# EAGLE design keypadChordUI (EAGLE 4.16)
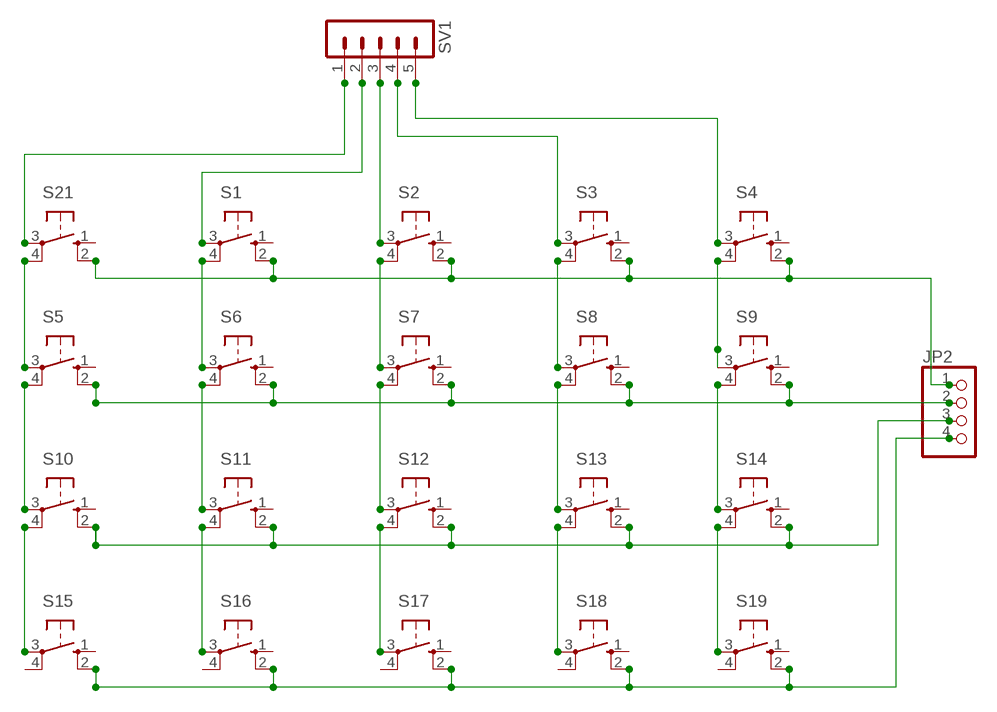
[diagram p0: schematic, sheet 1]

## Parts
JP2  PINHD-1X4  [1X04]
S1  10-XX  [B3F-10XX]
S2  10-XX  [B3F-10XX]
S3  10-XX  [B3F-10XX]
S4  10-XX  [B3F-10XX]
S5  10-XX  [B3F-10XX]
S6  10-XX  [B3F-10XX]
S7  10-XX  [B3F-10XX]
S8  10-XX  [B3F-10XX]
S9  10-XX  [B3F-10XX]
S10  10-XX  [B3F-10XX]
S11  10-XX  [B3F-10XX]
S12  10-XX  [B3F-10XX]
S13  10-XX  [B3F-10XX]
S14  10-XX  [B3F-10XX]
S15  10-XX  [B3F-10XX]
S16  10-XX  [B3F-10XX]
S17  10-XX  [B3F-10XX]
S18  10-XX  [B3F-10XX]
S19  10-XX  [B3F-10XX]
S21  10-XX  [B3F-10XX]
SV1  MA05-1  [MA05-1]

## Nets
N$1: S21.3(P) SV1.1
N$2: S10.4(P1) S15.3(P)
N$3: S4.3(P) SV1.5
N$4: S5.3(P) S21.4(P1)
N$5: S5.4(P1) S10.3(P)
N$7: S1.3(P) SV1.2
N$8: S1.4(P1) S6.3(P)
N$9: S6.4(P1) S11.3(P)
N$10: S2.3(P) SV1.3
N$11: S2.4(P1) S7.3(P)
N$12: S7.4(P1) S12.3(P)
N$13: S3.3(P) SV1.4
N$14: S3.4(P1) S8.3(P)
N$15: S8.4(P1) S13.3(P)
N$16: S14.4(P1) S19.3(P)
N$17: S9.4(P1) S14.3(P)
N$18: S4.4(P1) S9.3(P)
N$19: JP2.4 S15.2(S1) S16.2(S1) S17.2(S1) S18.2(S1) S19.2(S1)
N$21: S11.4(P1) S16.3(P)
N$22: JP2.1 S1.2(S1) S2.2(S1) S3.2(S1) S4.2(S1) S21.2(S1)
N$23: JP2.2 S5.2(S1) S6.2(S1) S7.2(S1) S8.2(S1) S9.2(S1)
N$24: JP2.3 S10.2(S1) S11.2(S1) S12.2(S1) S13.2(S1) S14.2(S1)
N$37: S12.4(P1) S17.3(P)
N$60: S13.4(P1) S18.3(P)
Unconnected: S1.1(S) S2.1(S) S3.1(S) S4.1(S) S5.1(S) S6.1(S) S7.1(S) S8.1(S) S9.1(S) S10.1(S) S11.1(S) S12.1(S) S13.1(S) S14.1(S) S15.1(S) S15.4(P1) S16.1(S) S16.4(P1) S17.1(S) S17.4(P1) S18.1(S) S18.4(P1) S19.1(S) S19.4(P1) S21.1(S)

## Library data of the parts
JP2 = pinhead:PINHD-1X4: PIN HEADER
S1-S19 S21 = switch-omron:10-XX: OMRON SWITCH
SV1 = con-lstb:MA05-1: PIN HEADER

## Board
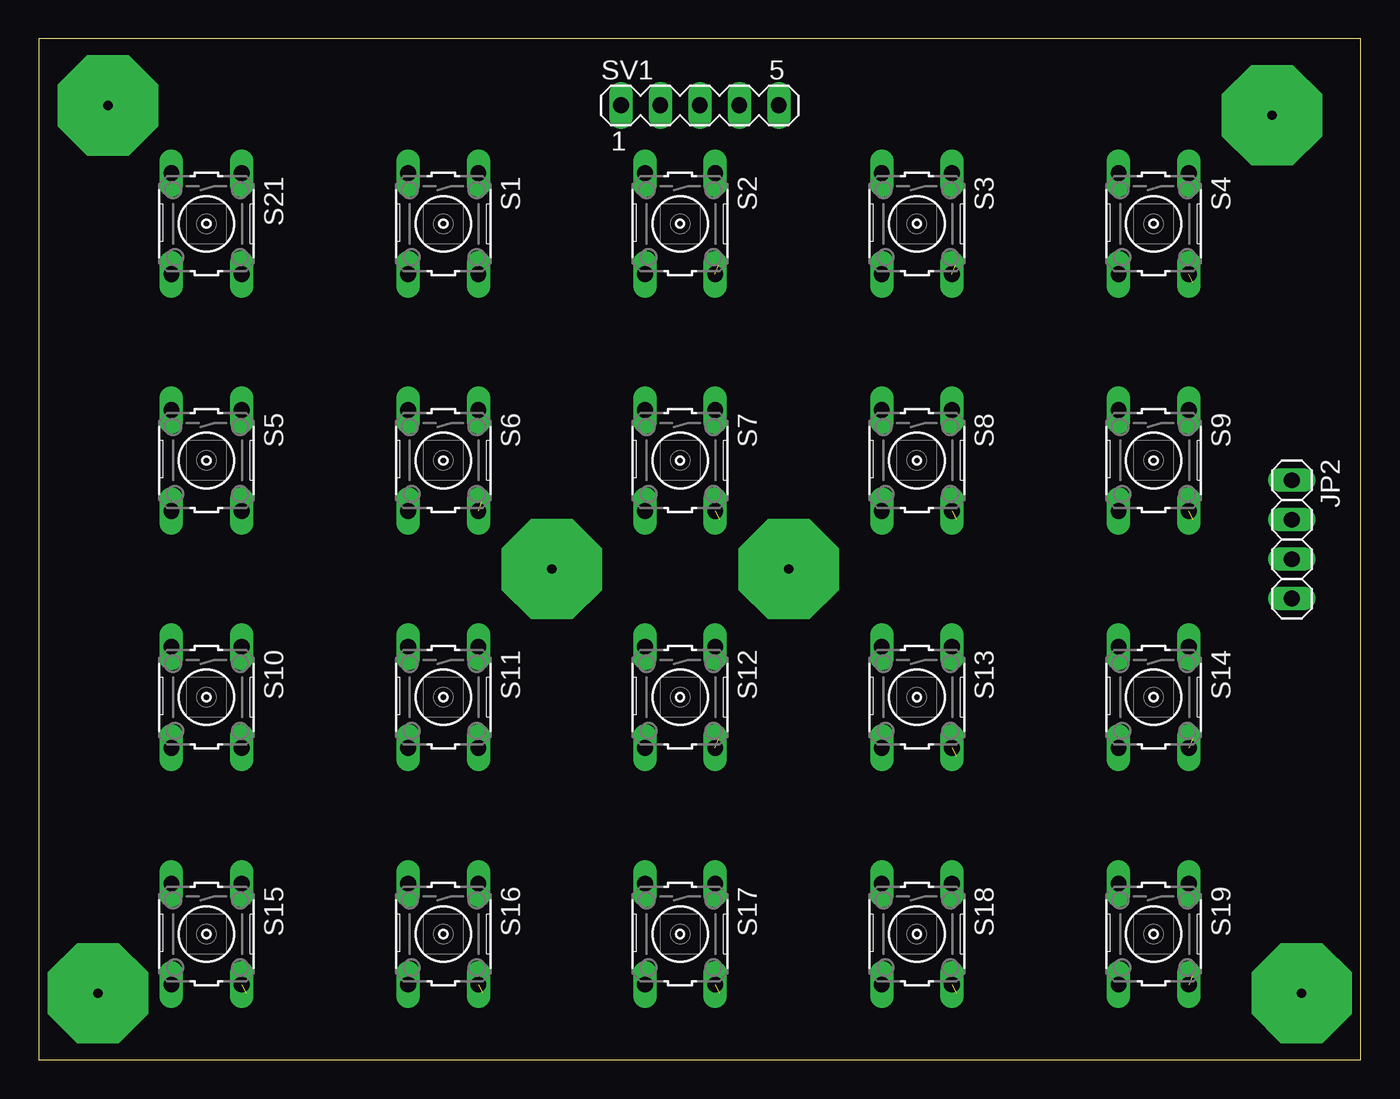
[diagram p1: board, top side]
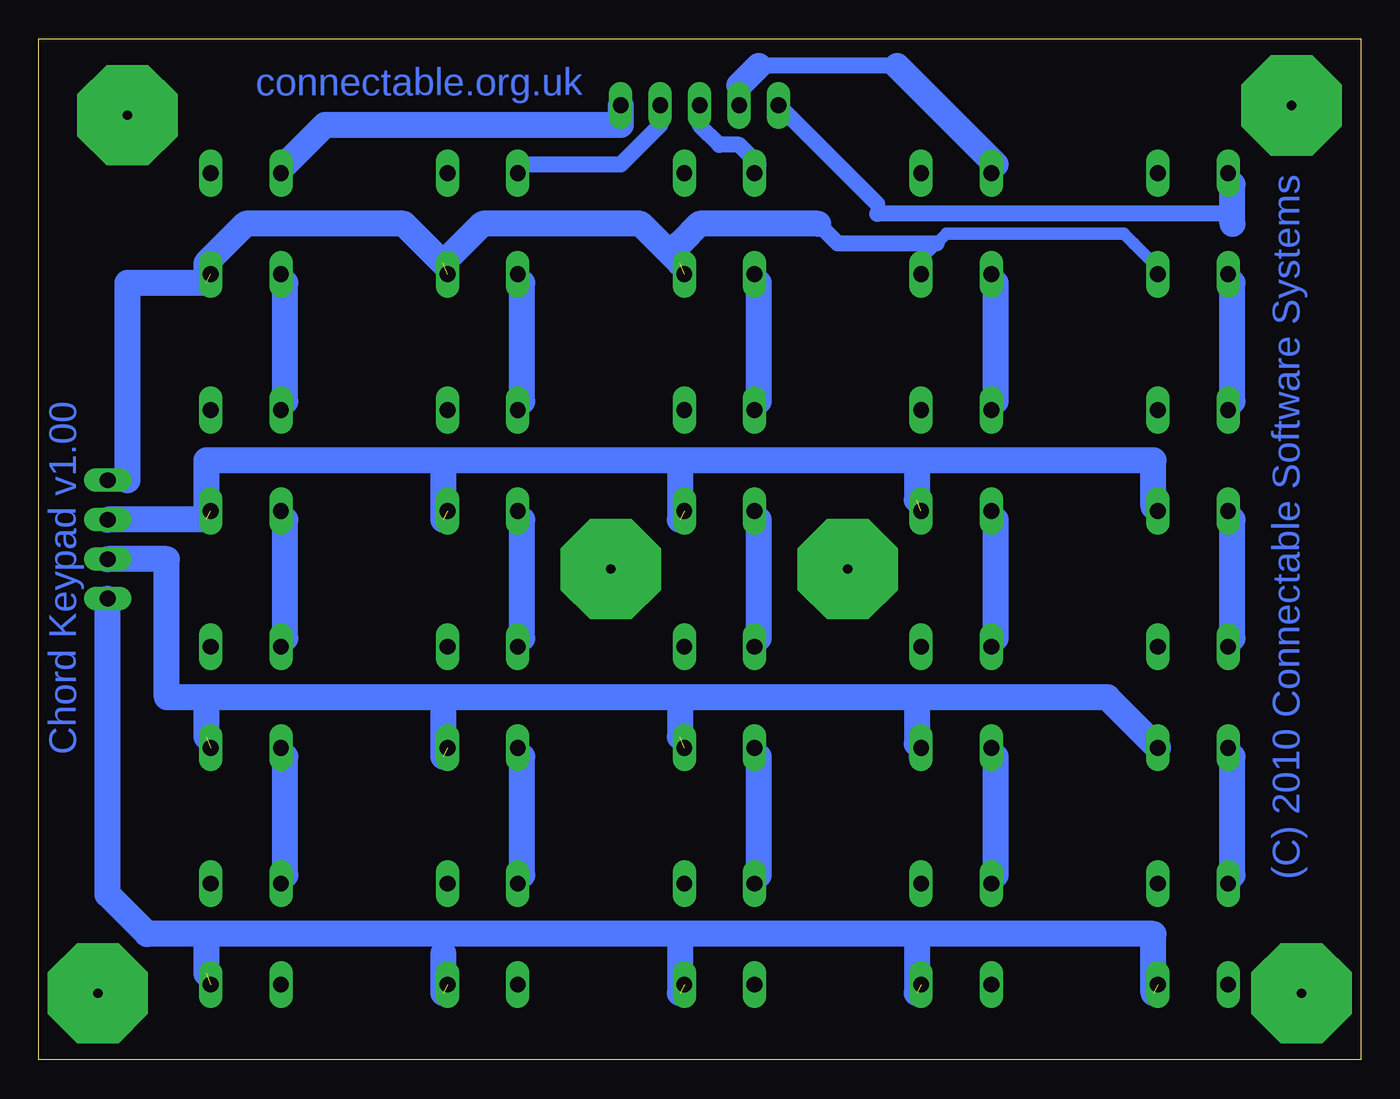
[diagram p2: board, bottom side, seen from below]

Size 85.07 x 65.71 mm. Coordinates in mm from the lower left corner, seen from the top.
Outline: 0,0 85.07,0 85.07,65.71 0,65.71 0,0
Copper layers (1*16): Top 0.035mm / dielectric 1.5mm / Bottom 0.035mm
Design rules "default": minimum track width 10mil, minimum drill 24mil, track to track 8mil, track to pad 8mil, pad to pad 8mil, via to via 8mil, smd to smd 8mil, copper to edge 40mil, drill to drill 8mil, minimum pad ring 10mil, minimum via ring 8mil, stop-mask expansion 4mil, vias tented up to drill 0mil, thermal gap 10mil

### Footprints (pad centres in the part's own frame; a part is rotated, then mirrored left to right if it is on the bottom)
1X04 = drill 1.016 long: 1 -3.81,0; 2 -1.27,0; 3 1.27,0; 4 3.81,0
B3F-10XX = drill 1.016 long: 1 -3.251,2.261; 2 3.251,2.261; 3 -3.251,-2.261; 4 3.251,-2.261
MA05-1 = drill 1.016 long: 1 -5.08,0; 2 -2.54,0; 3 0,0; 4 2.54,0; 5 5.08,0

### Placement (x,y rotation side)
JP2  80.64,33.49 270 top
S1  26.03,53.81 270 top
S2  41.27,53.81 270 top
S3  56.51,53.81 270 top
S4  71.75,53.81 270 top
S5  10.79,38.57 270 top
S6  26.03,38.57 270 top
S7  41.27,38.57 270 top
S8  56.51,38.57 270 top
S9  71.75,38.57 270 top
S10  10.79,23.33 270 top
S11  26.03,23.33 270 top
S12  41.27,23.33 270 top
S13  56.51,23.33 270 top
S14  71.75,23.33 270 top
S15  10.79,8.09 270 top
S16  26.03,8.09 270 top
S17  41.27,8.09 270 top
S18  56.51,8.09 270 top
S19  71.75,8.09 270 top
S21  10.79,53.81 270 top
SV1  42.54,61.43 0 top

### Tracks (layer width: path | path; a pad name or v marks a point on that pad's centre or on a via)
N$1
  Bottom 0.61: 8.89,54.45 8.25,53.81 | 31.11,55.08 31.11,54.45
  Bottom 1.016: 8.25,56.35 S21.3 | SV1.1 34.92,58.89 31.11,55.08 | 8.89,54.45 31.11,54.45
  Bottom 1.676: 8.25,53.81 8.25,56.35
N$2
  Bottom 1.016: S15.3 8.25,11.9 | 8.25,19.52 S10.4
  Bottom 1.676: 8.25,11.9 8.25,19.52
N$3
  Bottom 1.016: 69.21,57.62 S4.3
  Bottom 1.676: 69.21,57.62 66.67,60.16 47.62,60.16 SV1.5
N$4
  Bottom 1.016: S5.3 8.25,42.38 | 8.25,50 S21.4
  Bottom 1.676: 8.25,42.38 8.25,50
N$5
  Bottom 1.016: S10.3 8.25,27.14 | 8.25,34.76 S5.4
  Bottom 1.676: 8.25,27.14 8.25,34.76
N$6  (via drill 0.6 pad 6.45)
  other vias: 79.37,60.79
N$7
  Bottom 1.016: 29.84,63.97 38.73,63.97 | S1.3 23.49,57.62 | 40,62.7 SV1.2
  Bottom 1.676: 23.49,57.62 29.84,63.97 | 38.73,63.97 40,62.7
N$8
  Bottom 1.016: S6.3 23.49,42.38 | 23.49,50 S1.4
  Bottom 1.676: 23.49,42.38 23.49,50
N$9
  Bottom 1.016: S11.3 23.49,27.14 | 23.49,34.76 S6.4
  Bottom 1.676: 23.49,27.14 23.49,34.76
N$10
  Bottom 1.016: S2.3 38.73,57.62 40,58.89 41.27,58.89 42.54,60.16 SV1.3
N$11
  Bottom 1.016: S7.3 38.73,42.38 | 38.73,50 S2.4
  Bottom 1.676: 38.73,42.38 38.73,50
N$12
  Bottom 1.016: S12.3 38.73,27.14 | 38.73,34.76 S7.4
  Bottom 1.676: 38.73,27.14 38.73,34.76
N$13
  Bottom 1.016: SV1.4 45.08,60.16 47.62,57.62 53.97,57.62 S3.3
N$14
  Bottom 1.016: S8.3 53.97,42.38 | 53.97,50 S3.4
  Bottom 1.676: 53.97,42.38 53.97,50
N$15
  Bottom 1.016: S13.3 53.97,27.14 | 53.97,34.76 S8.4
  Bottom 1.676: 53.97,27.14 53.97,34.76
N$16
  Bottom 1.016: S19.3 69.21,11.9 | 69.21,19.52 S14.4
  Bottom 1.676: 69.21,11.9 69.21,19.52
N$17
  Bottom 1.016: S14.3 69.21,27.14 | 69.21,34.76 S9.4
  Bottom 1.676: 69.21,27.14 69.21,34.76
N$18
  Bottom 1.016: S9.3 69.21,42.38 | 69.21,50 S4.4
  Bottom 1.676: 69.21,42.38 69.21,50
N$19  (5 unrouted)
  Bottom 1.016: 59.05,8.09 59.05,6.82
  Bottom 1.676: 13.33,4.28 13.33,8.09 28.57,8.09 | 28.57,8.09 43.81,8.09 | 43.81,8.09 59.05,8.09 74.29,8.09 | 74.29,8.09 78.1,8.09 80.64,10.63 JP2.4 | 28.57,8.09 28.57,4.28 | 43.81,8.09 43.81,4.28 | 74.29,8.09 74.29,5.55 | 59.05,6.82 59.05,4.28
N$20  (via drill 0.6 pad 6.45)
  other vias: 81.27,4.28
N$21
  Bottom 1.016: S16.3 23.49,11.9 | 23.49,19.52 S11.4
  Bottom 1.676: 23.49,11.9 23.49,19.52
N$22  (3 unrouted)
  Bottom 0.813: S21.2 13.33,51.27 14.6,52.54 15.23,53.18 26.66,53.18 27.3,52.54 28.57,51.27 S1.2
  Bottom 1.016: 79.37,37.3 JP2.1 | 27.3,52.54 33.65,52.54 34.92,53.81 | 43.81,52.54 43.81,51.27
  Bottom 1.676: 79.37,37.3 79.37,50 74.29,50 74.29,51.27 71.75,53.81 61.59,53.81 59.05,51.27 56.51,53.81 46.35,53.81 43.81,51.27 | 34.92,53.81 42.54,53.81 43.81,52.54
N$23  (4 unrouted)
  Bottom 1.016: S5.2 13.33,35.6
  Bottom 1.676: 13.33,35.6 13.33,38.57 28.57,38.57 | 28.57,38.57 28.57,36.03 | 28.57,38.57 43.81,38.57 | 43.81,38.57 43.81,34.76 | 43.81,38.57 59.05,38.57 | 59.05,38.57 59.05,34.76 | 59.05,38.57 74.29,38.57 74.29,34.76 JP2.2
N$24  (3 unrouted)
  Bottom 1.016: 28.57,19.52 28.57,20.36 S11.2
  Bottom 1.676: S10.2 16.3,23.33 28.57,23.33 | 28.57,23.33 28.57,20.36 | 28.57,23.33 43.81,23.33 | 43.81,23.33 43.81,20.79 | 43.81,23.33 59.05,23.33 | 59.05,23.33 59.05,19.52 | 59.05,23.33 74.29,23.33 | 74.29,23.33 74.29,20.79 | 74.29,23.33 76.83,23.33 76.83,32.22 JP2.3
N$25  (via drill 0.6 pad 6.45)
  other vias: 4.44,61.43 3.81,4.28 33.02,31.59
N$26  (via drill 0.6 pad 6.45)
  other vias: 48.25,31.59
N$37
  Bottom 1.016: S17.3 38.73,11.9 | 38.73,19.52 S12.4
  Bottom 1.676: 38.73,11.9 38.73,19.52
N$60
  Bottom 1.016: S18.3 53.97,11.9 | 53.97,19.52 S13.4
  Bottom 1.676: 53.97,11.9 53.97,19.52

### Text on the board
Bottom: connectable.org.uk | (C) 2010 Connectable Software Systems | Chord Keypad v1.00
